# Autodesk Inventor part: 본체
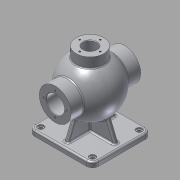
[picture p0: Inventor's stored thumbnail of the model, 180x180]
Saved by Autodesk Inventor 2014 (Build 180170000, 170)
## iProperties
Created: 2015-10
Part Number: 본체
Material: Aluminum 6061
Document SubType Name: Modeling
Designer: youjin09
Density: 2.71 g/cm^3
Appearance: Aluminum - Flat
Mass: 1509.57 g
Surface Area: 1153.7 cm^2
Volume: 557.037 cm^3
Author: youjin09
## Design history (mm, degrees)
sketch "Sketch1"
  geometry: L1 (-62.5, 57.5)-(62.5, 57.5); L2 (62.5, 57.5)-(62.5, -57.5); L3 (62.5, -57.5)-(-62.5, -57.5); L4 (-62.5, -57.5)-(-62.5, 57.5); L5 (-62.5, 57.5)-(62.5, -57.5); L6 (62.5, 57.5)-(-62.5, -57.5); 1 further point
  constraints: 12 end point, 2 midpoint, 2 parallel, 1 horizontal, 1 perpendicular
  dimensions: "d0" = 125 distance of L2.end L3.end; "d1" = 115 distance of L1.end L2.end
extrude "Extrusion1" new body sketch "Sketch1" distance "d2" = 10; taper "d3" = 0 deg
fillet "Fillet1" dims "d4" = 12
sketch "Sketch2"
  geometry: C1 r 6 at (-50.5, 45.5); C2 r 6 at (50.5, 45.5); C3 r 6 at (-50.5, -45.5); C4 r 6 at (50.5, -45.5); A1 r 12 centre (-50.5, 45.5) between (-50.5, 57.5) and (-62.5, 45.5) reference; A2 r 12 centre (-50.5, -45.5) between (-62.5, -45.5) and (-50.5, -57.5) reference; A3 r 12 centre (50.5, -45.5) between (50.5, -57.5) and (62.5, -45.5) reference; A4 r 12 centre (50.5, 45.5) between (62.5, 45.5) and (50.5, 57.5) reference; 1 further point
  constraints: 4 centre point, 4 coincident
  dimensions: "d6" = 12 diameter of C1; "d7" = 12 diameter of C2; "d8" = 12 diameter of C3; "d9" = 12 diameter of C4
extrude "Extrusion2" cut sketch "Sketch2" distance "d10" = 3; taper "d11" = 0 deg
sketch "Sketch3"
  geometry: C1 r 6 at (0, 0) reference; C2 r 6 at (0, 91) reference; C3 r 6 at (101, 91) reference; C4 r 6 at (101, 0) reference; C5 r 4 at (0, 0); C6 r 4 at (0, 91); C7 r 4 at (101, 91); C8 r 4 at (101, 0); 1 further point
  constraints: 4 centre point, 4 coincident
  dimensions: "d12" = 8 diameter of C5; "d13" = 8 diameter of C6; "d14" = 8 diameter of C7; "d15" = 8 diameter of C8
extrude "Extrusion3" cut sketch "Sketch3" stored distance "d16" = 3; taper "d17" = 0 deg
sketch "Sketch4"
  geometry: L1 (45.5, 0)-(-45.5, 0) reference; L2 (-53, 85)-(53, 85); A1 r 53 centre (0, 85) between (53, 85) and (-53, 85); 2 further points
  constraints: 2 end point, 2 point on circle, 1 centre point, 1 midpoint, 1 parallel, 1 vertical alignment
  dimensions: "d18" = 53 radius of A1; "d19" = 85 distance from line of L1 A1.centre; "d20" = 106 distance of L2.start L2.end
revolve "Revolution1" sketch "Sketch4" stored, may be unused: angle "d21" = 90 deg
workplane "Work Plane1"
sketch "Sketch5"
  geometry: C1 r 27 at (0, 0); 1 further point
  constraints: 1 centre point, 1 coincident
  dimensions: "d23" = 54 diameter of C1
extrude "Extrusion4" join sketch "Sketch5" stored distance "d24" = 3; taper "d25" = 0 deg
sketch "Sketch8"
  geometry: L1 (-57.5, 10)-(-57.5, 0) reference; L2 (-57.5, 10)-(-45.5, 10) reference; L3 (-45.5, 10)-(45.5, 10) reference; L4 (39.5, 10)-(51.5, 10) reference; L5 (45.5, 10)-(57.5, 10) reference; L6 (57.5, 10)-(57.5, 0) reference; L7 (33.719, 44.109)-(47.5, 10); L8 (-33.719, 44.109)-(-47.5, 10); A1 r 53 centre (0, 85) between (-27, 130.607) and (27, 130.607) reference; 1 further point
  constraints: 4 end point, 2 point on circle, 2 point on line
  dimensions: "d32" = 10 distance from line of L7.end L6; "d33" = 22 deg angle of L7 L6; "d34" = 10 distance from line of L8.end L1; "d35" = 22 deg angle of L8 L1
sketch "Sketch9"
  geometry: L1 (43, 85)-(-43, 85); A1 r 43 centre (0, 85) between (43, 85) and (-43, 85); 1 further point
  constraints: 2 end point, 2 point on circle, 1 centre point, 1 horizontal, 1 vertical alignment
  dimensions: "d38" = 43 radius of A1; "d39" = 85 distance of A1.centre point (0, 0); "d40" = 86 distance of L1.start L1.end
revolve "Revolution2" sketch "Sketch9" stored, may be unused: angle "d41" = 90 deg
workplane "Work Plane2"
sketch "Sketch11"
  geometry: C1 r 31 at (0, 85); 1 further point
  constraints: 1 centre point, 1 vertical alignment
  dimensions: "d45" = 62 diameter of C1; "d46" = 85 distance of point (0, 0) C1.centre
extrude "Extrusion7" join sketch "Sketch11" stored distance "d47" = 8; taper "d48" = 0 deg
mirror "Mirror1"
sketch "Sketch12"
  geometry: C1 r 31 at (0, 0) reference; C2 r 17.5 at (0, 0); 1 further point
  constraints: 1 centre point, 1 coincident
  dimensions: "d49" = 35 diameter of C2
extrude "Extrusion8" cut sketch "Sketch12" distance "d50" = 16; taper "d51" = 0 deg
sketch "Sketch13"
  geometry: C1 r 17.5 at (0, 0) reference; C2 r 18.5 at (0, 0); 1 further point
  constraints: 1 centre point, 1 coincident
  dimensions: "d52" = 37 diameter of C2
extrude "Extrusion9" cut sketch "Sketch13" distance "d53" = 1.75; taper "d54" = 0 deg
sketch "Sketch14"
  geometry: C1 r 18.5 at (0, 0) reference; C2 r 17.5 at (0, 0); 1 further point
  constraints: 1 centre point, 1 coincident
  dimensions: "d55" = 35 diameter of C2
extrude "Extrusion10" cut sketch "Sketch14" distance "d56" = 30; taper "d57" = 0 deg
sketch "Sketch15"
  geometry: C1 r 31 at (0, 0) reference; C2 r 17.5 at (0, 0); 1 further point
  constraints: 1 centre point, 1 coincident
  dimensions: "d58" = 35 diameter of C2
extrude "Extrusion11" cut sketch "Sketch15" distance "d59" = 50; taper "d60" = 0 deg
sketch "Sketch16"
  geometry: C1 r 17.5 at (0, 0) reference; C2 r 31 at (0, 0) reference; A1 r 22.5 centre (0, 0) between (-22.5, 0) and (0, 22.5); 3 further points
  constraints: 4 point on circle, 2 horizontal alignment, 2 vertical alignment, 1 centre point, 1 coincident
  dimensions: "d61" = 45 diameter of A1
hole "Hole1" sketch "Sketch16" at (0, 22.5), (0, -22.5), (-22.5, 0), (22.5, 0) diameter "d62" = 3.242; stored, may be unused: countersink angle "d66" = 90 deg, drill point angle "d68" = 118 deg; dims "d63" = 12, "d64" = 4, "d65" = 2, "d67" = 15
sketch "Sketch17"
  geometry: C1 r 17.5 at (0, 0) reference; C2 r 31 at (0, 0) reference; A1 r 24 centre (0, 0) between (0, 24) and (-24, 0); 3 further points
  constraints: 4 point on circle, 2 horizontal alignment, 2 vertical alignment, 1 centre point, 1 coincident
  dimensions: "d69" = 48 diameter of A1
hole "Hole2" sketch "Sketch17" at (0, 24), (0, -24), (-24, 0), (24, 0) diameter "d70" = 3.242; stored, may be unused: countersink angle "d74" = 90 deg, drill point angle "d76" = 118 deg; dims "d71" = 16, "d72" = 4, "d73" = 2, "d75" = 19
sketch "Sketch18"
  geometry: C1 r 27 at (0, 0) reference; C2 r 13 at (0, 0)
  constraints: 1 centre point, 1 coincident
  dimensions: "d77" = 26 diameter of C2
extrude "Extrusion12" cut sketch "Sketch18" distance "d78" = 50; taper "d79" = 0 deg
sketch "Sketch19"
  geometry: C1 r 13 at (0, 0) reference; C2 r 27 at (0, 0) reference; A1 r 20 centre (0, 0) between (0, 20) and (20, 0); 2 further points
  constraints: 4 point on circle, 2 horizontal alignment, 2 vertical alignment, 1 centre point, 1 coincident
  dimensions: "d80" = 40 diameter of A1
hole "Hole3" sketch "Sketch19" at (0, 20), (0, -20), (-20, 0), (20, 0) diameter "d81" = 3.242; stored, may be unused: countersink angle "d85" = 90 deg, drill point angle "d87" = 118 deg; dims "d82" = 9, "d83" = 4, "d84" = 2, "d86" = 11
workplane "Work Plane3"
sketch "Sketch21"
  geometry: L1 (45.5, 0)-(-45.5, 0) reference; L2 (-27, 150)-(27, 150) reference; L3 (-27, 130.607)-(27, 130.607) reference; L4 (-27, 150)-(27, 150) reference; 3 further points
  constraints: 1 midpoint, 1 vertical alignment, 1 other
  dimensions: "d89" = 10 distance from line of point (0, 140) L2; "d97" = 27 horizontal distance of point (0, 140) L2.start (derived)
emboss "Emboss1" sketch "Sketch21" dims "d90" = 0.5, "d91" = 0
chamfer "Chamfer1" distance "d92" = 1; stored, may be unused: second distance "d93" = 2, angle "d94" = 45 deg
fillet "Fillet2" dims "d95" = 3
sketch "Sketch22"
  geometry: L1 (-4, 4)-(4, 4); L2 (4, 4)-(4, -4); L3 (4, -4)-(-4, -4); L4 (-4, -4)-(-4, 4); L5 (-4, 4)-(4, -4); L6 (4, 4)-(-4, -4); 1 further point
  constraints: 12 end point, 2 midpoint, 2 parallel, 1 horizontal, 1 perpendicular
  dimensions: "d98" = 8 distance of L2.end L3.end; "d99" = 8 distance of L1.end L2.end
extrude "Extrusion13" join sketch "Sketch22" stored distance "d100" = 10; taper "d101" = 0 deg
feature "Rib1" dims "d102" = 1, "d103" = 8, "d104" = 0, "d105" = 0, "d106" = 1, "d107" = 1
feature "Rib2" dims "d108" = 1, "d109" = 8, "d110" = 0, "d111" = 0, "d112" = 1, "d113" = 1
sketch "Sketch23"
  geometry: L1 (-62.5, 0)-(-62.5, 7) reference; L2 (-59.5, 10)-(-50.5, 10) reference; L3 (-56.5, 10)-(-44.5, 10) reference; L4 (-50.5, 10)-(50.5, 10) reference; L5 (44.5, 10)-(56.5, 10) reference; L6 (50.5, 10)-(59.5, 10) reference; L7 (62.5, 7)-(50.5, 7) reference; L8 (62.5, 7)-(62.5, 0) reference; L9 (62.5, 0)-(50.5, 0) reference; L10 (50.5, 0)-(50.5, 7) reference; L11 (-37.379, 47.426)-(-52.5, 10); L12 (37.379, 47.426)-(52.5, 10); A1 r 53 centre (0, 85) between (-28.393, 129.753) and (28.393, 129.753) reference; 1 further point
  constraints: 4 end point, 2 point on circle, 2 point on line
  dimensions: "d114" = 10 distance from line of L11.end L1; "d115" = 22 deg angle of L1 L11; "d116" = 10 distance from line of L12.end L8; "d117" = 22 deg angle of L12 L8
  node "Projected Loop4"
feature "Rib3" dims "d118" = 1, "d119" = 8, "d120" = 0, "d121" = 0, "d122" = 1, "d123" = 1
feature "Rib4" dims "d124" = 1, "d125" = 8, "d126" = 0, "d127" = 0, "d128" = 1, "d129" = 1
fillet "Fillet4" dims "d130" = 3
body "Solid1"
node "Projected Loop1"
node "Projected Loop2"
node "Projected Loop3"
other parameters: "d44" = 68, "d88" = -27.5
